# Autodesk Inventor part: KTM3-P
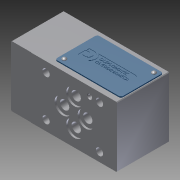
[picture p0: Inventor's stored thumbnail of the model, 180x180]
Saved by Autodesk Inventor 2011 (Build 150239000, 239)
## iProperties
Created: 2012-01
Part Number: KTM3-P
Document SubType Name: Modeling
Designer: khramov
Density: 1 g/cm^3
Author: khramov
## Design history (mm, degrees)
derived "KTM3_P_10N.iam"
node "Твердое тело1"
node "0134963.ipt:1"
sketch "3001110000.ipt:1"
sketch "0530521.ipt:1"
sketch "0530521.ipt:2"
